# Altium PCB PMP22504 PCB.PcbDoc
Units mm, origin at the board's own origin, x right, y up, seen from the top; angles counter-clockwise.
Board outline 85 x 42.5 mm, 2 copper layers (Top Layer, Bottom Layer), stack 1.575 mm thick; 21 components, 12 nets, 56 pads, 21 vias.
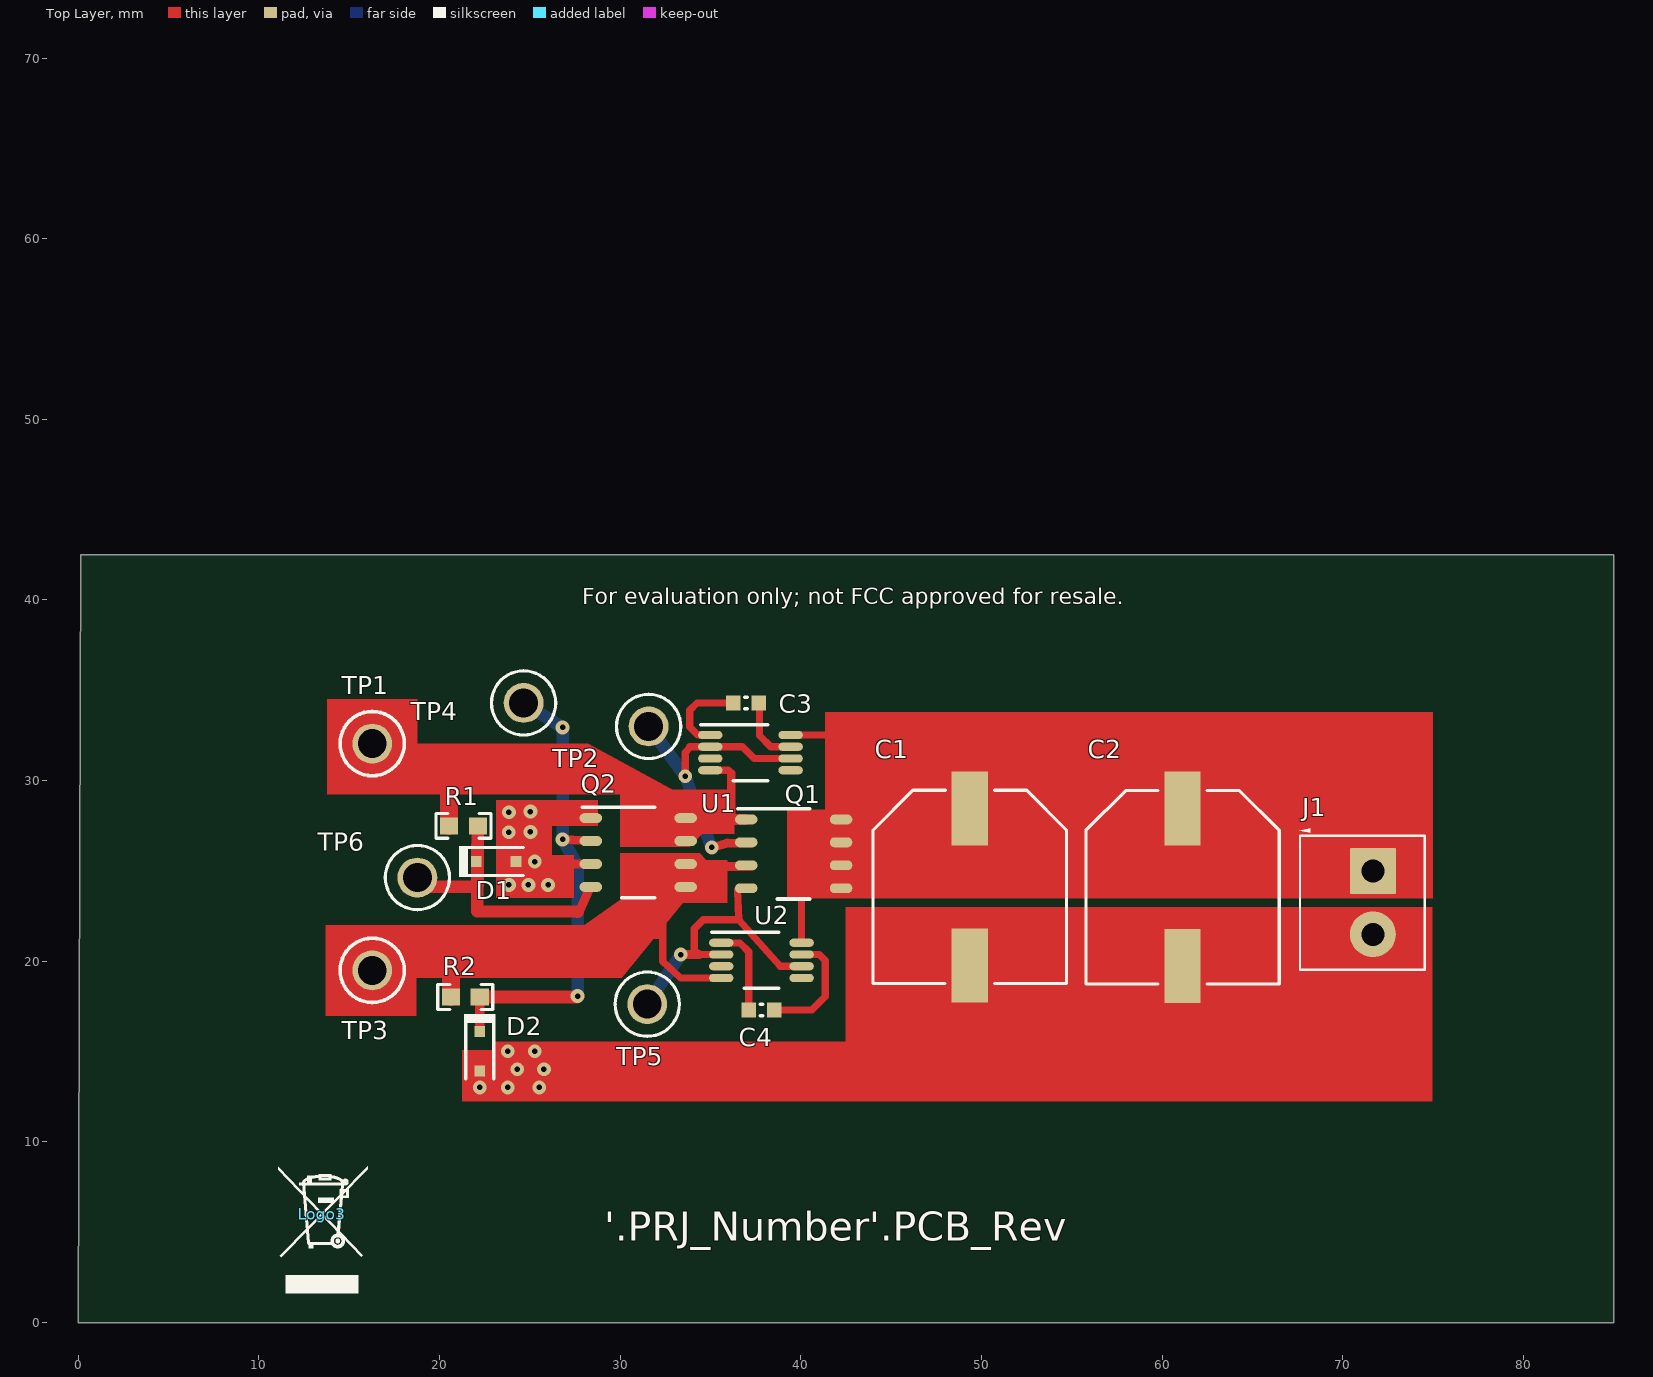
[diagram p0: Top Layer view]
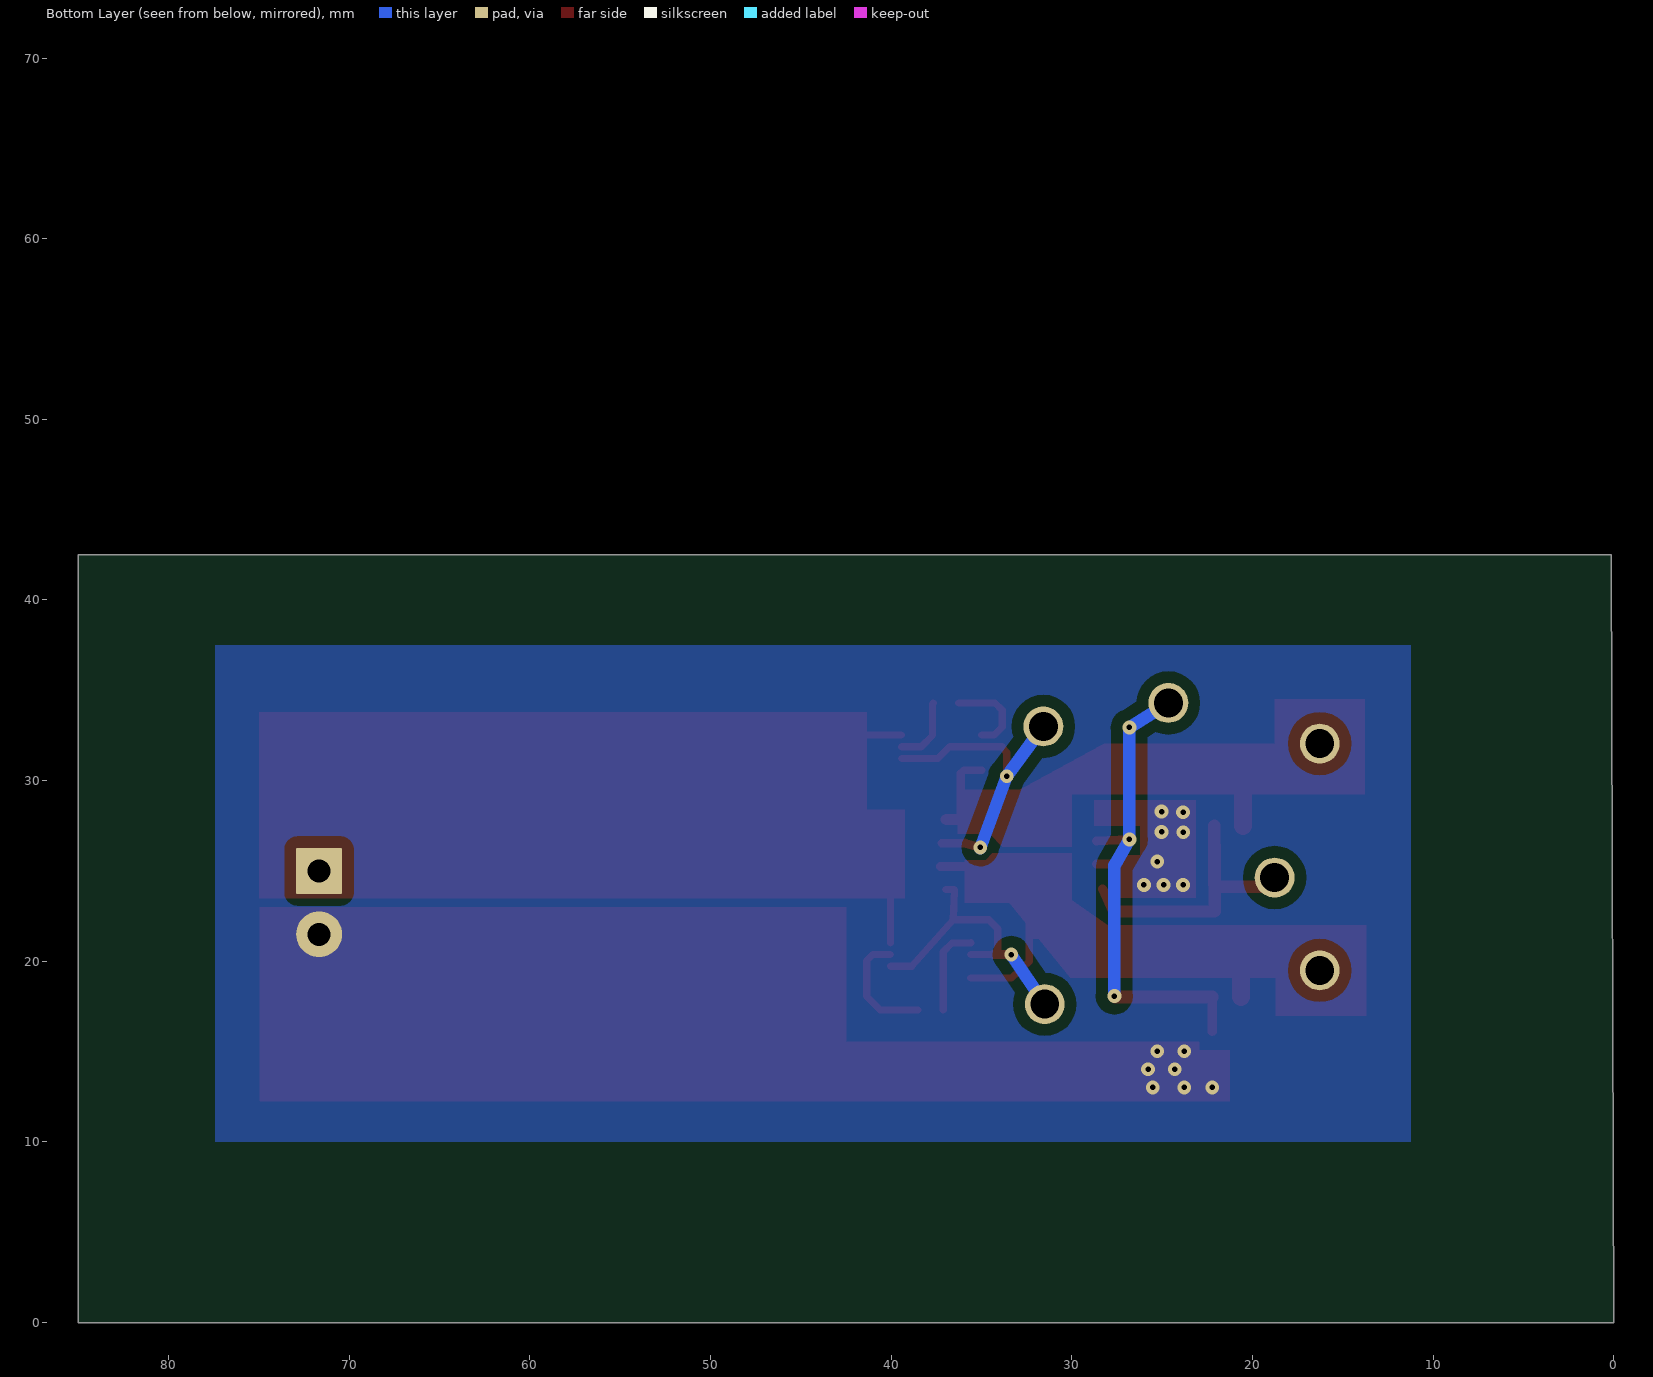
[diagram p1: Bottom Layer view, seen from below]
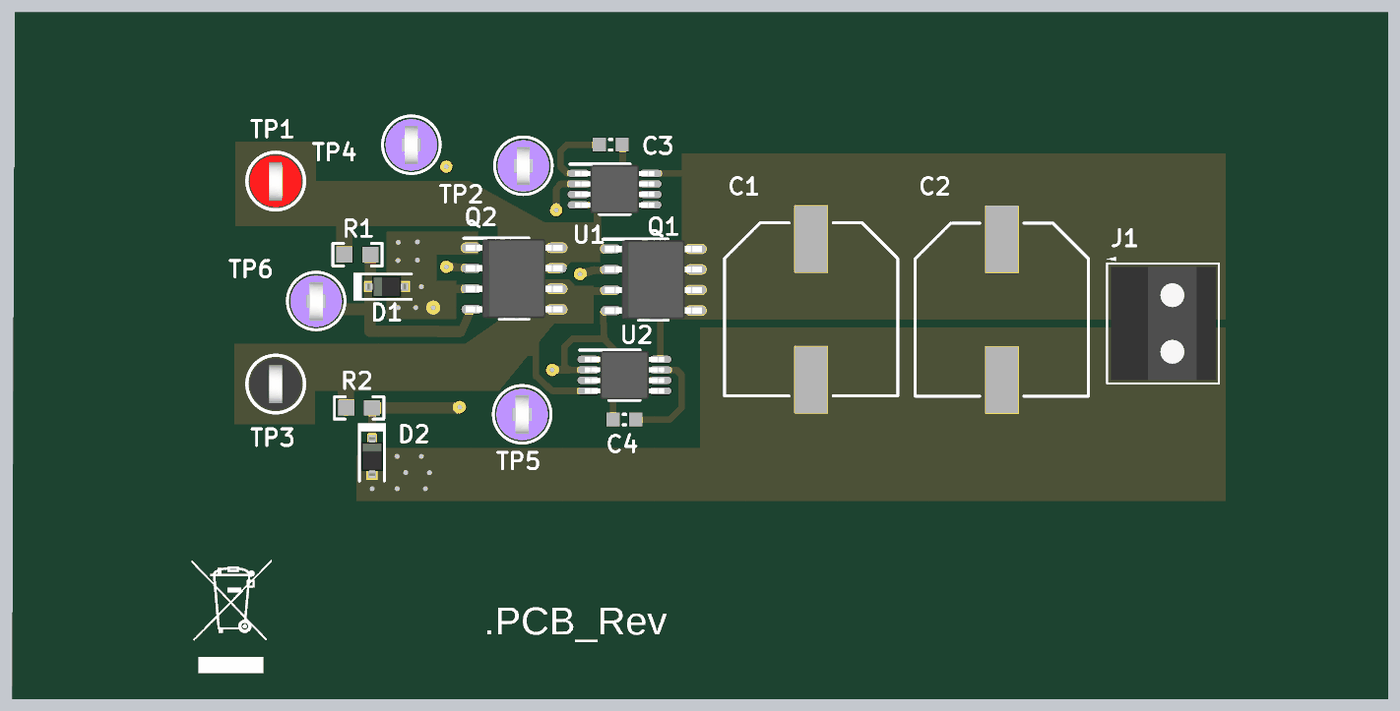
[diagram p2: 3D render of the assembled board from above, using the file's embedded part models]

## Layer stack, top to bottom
Top Solder: solder mask 0.0102, Solder Resist, Dk 3.5
Top Layer: signal copper 0.0356
Dielectric1: core 1.5037, FR-4, Dk 4.8
Bottom Layer: signal copper 0.0356
Bottom Solder: solder mask 0.0102, Solder Resist, Dk 3.5

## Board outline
0,0 85,0 85,42.5 0.142,42.5

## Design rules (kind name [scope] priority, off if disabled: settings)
AcuteAngle [All] p1: minimum=4.50000000000000E+0001 checktracksonly=FALSE
AssemblyTestPointUsage [All] p1: valid=2
BoardOutlineClearance BoardOutlineClearance_MountingHoles [OnCopper and InComponentClass('Mounting Holes')] p1: gap=1 ignorepadtopadclearanceinfootprint=FALSE
BoardOutlineClearance BoardOutlineClearance_Poly [OnCopper and IsPoly] p2: gap=0.635 ignorepadtopadclearanceinfootprint=FALSE
BoardOutlineClearance [OnCopper and Not InComponentClass('Logo') and not InComponentClass('FiducialMark') and not InRegion(1000,500,4000,800) and not InPoly] p3: gap=1.905 ignorepadtopadclearanceinfootprint=FALSE
Clearance Clearance_Keepouts [((IsTrack Or IsArc) And Not InPoly) And IsFree and IsKeepOut vs ((IsTrack Or IsArc) And Not InPoly) And IsFree and IsKeepOut] p1: gap=0 ignorepadtopadclearanceinfootprint=FALSE
Clearance Clearance_Poly [InPolygon] p2: gap=0.635 ignorepadtopadclearanceinfootprint=TRUE
Clearance Clearance_FiducialMark [IsKeepOut and InComponentClass('FiducialMark') vs IsPad and InComponentClass('FiducialMark')] p3: gap=0 ignorepadtopadclearanceinfootprint=FALSE
Clearance [All] p4: gap=0.2 ignorepadtopadclearanceinfootprint=TRUE
ComponentClearance ComponentClearance_MountingHoles_FiducialMarks [InComponentClass('Mounting Holes') vs InComponentClass('FiducialMark')] p1: gap=1.27 collisioncheckmode=3 verticalgap=0.254 showdistances=FALSE
ComponentClearance ComponentClearance_Shunt [InComponentClass('Header') vs InComponentClass('Shunt')] p2: gap=0 collisioncheckmode=3 verticalgap=0 showdistances=FALSE
ComponentClearance ComponentClearance_Logo [InComponentClass('Logo')] p3: gap=1.27 collisioncheckmode=3 verticalgap=0.254 showdistances=FALSE
ComponentClearance ComponentClearance_ScrewToNut [(HasFootprint('NY PMS 440 0025 PH')) vs (HasFootprint('Keystone_1902C'))] p4: gap=0.127 collisioncheckmode=3 verticalgap=0.254 showdistances=FALSE
ComponentClearance ComponentClearance_MountingHoles [InComponentClass('Mounting Holes')] p5: gap=6.35 collisioncheckmode=3 verticalgap=2540 showdistances=FALSE
ComponentClearance ComponentClearance_SmallPassives [HasFootprint('0201*') or HasFootprint('0402*') or HasFootprint('0508') or HasFootprint('0603*') or HasFootprint('0612') or HasFootprint('0805*') or HasFootprint('0815*') or HasFootprint('0830*') or HasFootprint('1206*') or HasFootprint('1210*') or HasFootprint('1808*') or HasFootprint('1812*') or HasFootprint('1825*') or HasFootprint('2010*') or HasFootprint('2220*') or HasFootprint('2225*') or HasFootprint('2512*') or HasFootprint('2728*') or HasFootprint('3518*') vs HasFootprint('0201*') or HasFootprint('0402*') or HasFootprint('0508') or HasFootprint('0603*') or HasFootprint('0612') or HasFootprint('0805*') or HasFootprint('0815*') or HasFootprint('0830*') or HasFootprint('1206*') or HasFootprint('1210*') or HasFootprint('1808*') or HasFootprint('1812*') or HasFootprint('1825*') or HasFootprint('2010*') or HasFootprint('2220*') or HasFootprint('2225*') or HasFootprint('2512*') or HasFootprint('2728*') or HasFootprint('3518*')] p6: gap=0.38 collisioncheckmode=3 verticalgap=0.254 showdistances=FALSE
ComponentClearance ComponentClearance_THtoSMT [IsThruComponent vs IsSMTComponent] p7: gap=1.016 collisioncheckmode=3 verticalgap=0.762 showdistances=FALSE
ComponentClearance ComponentClearance_THtoTH [IsThruComponent vs IsThruComponent] p8: gap=0.762 collisioncheckmode=3 verticalgap=0.762 showdistances=FALSE
ComponentClearance [All] p9: gap=0.762 collisioncheckmode=3 verticalgap=0.254 showdistances=FALSE
DiffPairsRouting [All] p1: maxlimit=2.54 minlimit=0.254 mostfreqgap=0.254 toplayer_minwidth=0.381 toplayer_maxwidth=0.381 toplayer_prefwidth=0.381 bottomlayer_minwidth=0.381 bottomlayer_maxwidth=0.381 bottomlayer_prefwidth=0.381 maxuncoupledlength=25.4
FabricationTestPointUsage TestPointUsage [All] p1: valid=2 allowmultiple=FALSE
FabricationTestpoint Testpoint [All] p1: side=3 testpointundercomponent=TRUE minsize=1.016 maxsize=2.54 preferedsize=1.524 minholesize=0 maxholesize=1.016 preferedholesize=0.813 testpointgrid=0.025 allowsidetop=TRUE allowsidebottom=TRUE usegrid=TRUE gridtolerance=0
FanoutControl Fanout_LCC [IsLCC] p1: bgadir=Out bgaviamode=Centered fanoutstyle=Auto fanoutdirection=Alternating viagrid=0.025 // Fanout_LCC (Default Rule)
FanoutControl Fanout_BGA [IsBGA] p2: bgadir=Out bgaviamode=Centered fanoutstyle=Auto fanoutdirection=Alternating viagrid=0.025 // Fanout_BGA (Default Rule)
FanoutControl Fanout_Default [All] p4: bgadir=Out bgaviamode=Centered fanoutstyle=Auto fanoutdirection=Alternating viagrid=0.025 // Fanout_Default (Default Rule)
FanoutControl Fanout_Small [(CompPinCount < 5)] p5: bgadir=Out bgaviamode=Centered fanoutstyle=Auto fanoutdirection=OutThenIn viagrid=0.025 // Fanout_Small (Default Rule)
HoleSize [All] p1: absolutevalues=TRUE maxlimit=6.375 minlimit=0.2 maxpercent=80.000 minpercent=20.000
MinimumAnnularRing MinimumAnnularRing_ThermalPadVias [IsVia and InAnyComponent] p1: minimumring=0.15
MinimumAnnularRing [All] p2: minimumring=0.2
MinimumSolderMaskSliver MinimumSolderMaskSliver_Logo [InComponentClass('Logo') vs InComponentClass('Logo')] p1: minsoldermaskwidth=0.018
MinimumSolderMaskSliver [All] p2: minsoldermaskwidth=0.1
PlaneConnect [All] p1: planeconnectstyle=Relief reliefexpansion=0.254 reliefentries=4 reliefconductorwidth=0.254 reliefairgap=0.254
PolygonConnect [All] p1: connectstyle=Direct reliefconductorwidth=0.254 reliefentries=4 polygonreliefangle="90 Angle" airgapwidth=0.254
RoutingVias ThermalPadVias [IsVia and InAnyComponent] p1: holewidth=0.2 width=0.5 viastyle="Through Hole" minholewidth=0.2 minwidth=0.5 maxholewidth=0.33 maxwidth=0.6
RoutingVias [All] p2: holewidth=0.406 width=0.864 viastyle="Through Hole" minholewidth=0.2 minwidth=0.66 maxholewidth=1.016 maxwidth=1.651
SilkToBoardRegionClearance [Not ((IsComment or IsDesignator) And (Hide <> 'False')) and not InRegion(1000,500,4000,800)] p1:
SilkToSilkClearance SilkToSilkClearance_Pb-FreeLogo [(HasFootprint('Pb-Free_Overlay_Medium') OR HasFootprint('Pb-Free_Overlay_Small')) vs (HasFootprint('Pb-Free_Overlay_Medium') OR HasFootprint('Pb-Free_Overlay_Small'))] p1: silktosilkclearance=0
SilkToSilkClearance [All] p2: silktosilkclearance=0.1
SilkToSolderMaskClearance SilkToComponentPadClearance [(IsPad or IsFill or IsRegion) and InAnycomponent] p1: minsilkscreentomaskgap=0.127 clearancetoexposedcopper=TRUE
SilkToSolderMaskClearance "Silk to Solder Mask Opening" [All] p2: minsilkscreentomaskgap=0.1 clearancetoexposedcopper=FALSE
SolderMaskExpansion [All] p1: expansion=0.05
UnRoutedNet [All] p1: checkbadconnections=TRUE
Width [All] p1: maxlimit=2.54 minlimit=0.152 preferedwidth=0.254 checkconnectedcopper=TRUE
14 further rules are at their usual default settings.

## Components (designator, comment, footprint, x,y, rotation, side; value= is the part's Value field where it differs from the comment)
C1 "CBULK" SM_RADIAL_G 49.351,24.117 r270 top value=220uF
C2 "CBULK" SM_RADIAL_G 61.132,24.101 r270 top value=330uF
C3 "GRM188Z71C225KE43" 0603L 36.97,34.301 r180 top value=2.2uF
C4 "GRM188Z71C225KE43" 0603L 37.817,17.301 r180 top value=2.2uF
D1 "MMSZ5242BS-7-F" SOD-323 23.129,25.524 r0 top value=12V
D2 "MMSZ5242BS-7-F" SOD-323 22.228,15.022 r270 top value=12V
J1 "ED555/2DS" TERM_BLK_ED555-2DS 71.667,25 r270 top
Logo2 "FCC disclaimer" FCC_disclaimer 0.5,-26.75 r0 top
Logo3 "WEEE logo" WEEE_Minimum 13.5,6 r0 top
Q1 "CSD88539ND" D0008A_L 39.603,25.951 r0 top value=60V
Q2 "CSD88539ND" D0008A_L 31,26.022 r0 top value=60V
R1 "RC0603FR-0712KL" 0603 21.326,27.499 r180 top value=12.0k
R2 "RC0603FR-0712KL" 0603 21.428,18.022 r180 top value=12.0k
TP1 "LINE" Keystone5010 16.276,32.051 r0 top
TP2 "5129" Keystone5129 31.576,33 r0 top
TP3 "NEUTRAL" Keystone5011 16.276,19.5 r0 top
TP4 "5129" Keystone5129 24.654,34.301 r0 top
TP5 "5129" Keystone5129 31.499,17.626 r0 top
TP6 "5129" Keystone5129 18.776,24.636 r0 top
U1 "LM74610QDGKRQ1" DGK0008A_N 37.209,31.551 r0 top
U2 "LM74610QDGKRQ1" DGK0008A_N 37.817,20.051 r0 top

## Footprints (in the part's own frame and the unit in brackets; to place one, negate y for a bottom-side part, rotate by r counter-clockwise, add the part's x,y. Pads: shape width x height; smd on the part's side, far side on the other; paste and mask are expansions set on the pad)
0603 [mm] "0603 from SM-752 data"
  rect 1x0.95 smd: 1(-0.8,0) 2(0.8,0)
  silkscreen extent -1.52,-0.69 1.52,0.69, body extent -0.87,-0.47 0.87,0.47, height 1
0603L [mm] "0603 from SM-752 data"
  rect 0.8x0.85 smd: 1(-0.7,0) 2(0.7,0)
  silkscreen extent -0.07,-0.33 0.07,0.33, body extent -0.87,-0.47 0.87,0.47, height 1
D0008A_L [mm] "SOIC, 8-Leads, Body 4.9x3.9mm, Pitch 1.27mm, IPC High Density"
  oval 1.25x0.55 smd: 1(-2.625,1.905) 2(-2.625,0.635) 3(-2.625,-0.635) 4(-2.625,-1.905) 5(2.625,-1.905) 6(2.625,-0.635) 7(2.625,0.635) 8(2.625,1.905)
  silkscreen extent -3.1,-2.5 0.9,2.5, body extent -3,-2.45 3,2.45, height 1.63
DGK0008A_N [mm] "TSOP, 8-Leads, Body 3x3mm, Pitch 0.65mm, IPC Medium Density"
  oval 1.35x0.45 smd: 1(-2.225,0.975) 2(-2.225,0.325) 3(-2.225,-0.325) 4(-2.225,-0.975) 5(2.225,-0.975) 6(2.225,-0.325) 7(2.225,0.325) 8(2.225,0.975)
  silkscreen extent -2.75,-1.55 0.95,1.55, body extent -2.45,-1.5 2.45,1.5, height 0.96
FCC_disclaimer [mm]
Keystone5010 [mil] "Keystone Multipurpose loops"
  round 87 hole 63: 1(0,0)
  silkscreen extent -70,-70 70,70, body extent -63,-63 63,62, height 319
Keystone5011 [mil] "Keystone Multipurpose loops"
  round 87 hole 63: 1(0,0)
  silkscreen extent -70,-70 70,70, body extent -63,-63 63,62, height 319
Keystone5129 [mil] "Keystone Multipurpose loops"
  round 87 hole 63: 1(0,0)
  silkscreen extent -70,-70 70,70, body extent -63,-63 63,62, height 319
SM_RADIAL_G [mm] "10 x 10.2mm:  Panasonic G"
  rect 4.1x2 smd: 1(-4.35,0) 2(4.35,0)
  silkscreen extent -5.35,-5.35 5.35,5.35, body extent -5.25,-5.25 5.25,5.25, height 10.5
SOD-323 [mm] "NXP recommended land pattern"
  rect 0.6x0.6 smd paste-0.05: 1(-1.1,0) 2(1.1,0)
  silkscreen extent -2.06,-0.86 1.53,0.86, body extent -1.3,-0.67 1.3,0.68, height 1.1
TERM_BLK_ED555-2DS [mil]
  rrect4% 100x100 hole 50: 1(0,0)
  round 100 hole 50: 2(138,0)
  silkscreen extent -93,-161 215,113, body extent -69,-150 207,106, height 323
WEEE_Minimum [mm] "WEEElie bin"
  silkscreen extent -2.42,-4.38 2.52,2.65

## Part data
C1: library part CMP-0011180-2, "CAP, AL, 220 uF, 50 V, +/- 20%, 0.18 ohm, AEC-Q200 Grade 2, SMD", Cap_Case=G, Manufacturer=Panasonic, PartNumber=EEE-FK1H221GP, Supplier Part Number 1=PCE4324CT-ND, Tolerance_%=20%, Value1="0.18 ohm", Value2=50V, ValueDisplayed=220uF
C2: library part CMP-0860442-1, "CAP, AL, 330 µF, 50 V, +/- 20%, 0.12 ohm, AEC-Q200 Grade 2, SMD", Cap_Case=10x10.2mm, Manufacturer=Panasonic, PartNumber=EEE-FT1H331AP, Tolerance_%=20%, Value1="0.12 ohm", Value2=50V, ValueDisplayed=330µF
C3 C4: library part CMP-0007499-1, "CAP, CERM, 2.2 uF, 16 V, +/- 10%, X7R, 0603", Cap_Case=0603, Manufacturer=MuRata, Supplier Part Number 1=81-GRM188Z71C225KE3D, TempCo=X7R, Tolerance_%=10%, Value1=Unknown, Value2=16V, ValueDisplayed=2.2uF
D1 D2: library part CMP-0005831-4, "Diode, Zener, 12 V, 200 mW, SOD-323", Manufacturer="Diodes Inc.", Power_W=200mW, Value1=0.2W
J1: library part CMP-0074913-1, "Terminal Block, 3.5mm Pitch, 2x1, TH", Color=Grey, Current_A=6A, Manufacturer="On-Shore Technology", Supplier Part Number 1=ED1514-ND, Voltage_V=150V
Logo2: library part CMP-0074847-1, "FCC_disclaimer"
Logo3: library part CMP-0074769-1
Q1 Q2: library part CMP-0000829-2, "MOSFET, 2-CH, N-CH, 60 V, 6.3 A, D0008A (SOIC-8)", Alternate Manufacturer=None, Manufacturer="Texas Instruments", Supplier Part Number 1=296-37304-1-ND, Value2="7.2 nC"
R1 R2: library part CMP-0022779-5, "RES, 12.0 k, 1%, 0.1 W, 0603", Manufacturer=Yageo, Power_W=100mW, Supplier Part Number 1=311-12.0KHRCT-ND, TempCo="100 ppm/C", Tolerance_%=1%, Value2=0.1W, Value_Code=12k0, ValueDisplayed=12.0k
TP1: library part CMP-0055147-1, "Test Point, Multipurpose, Red, TH", Color=Red, Manufacturer=Keystone, PartNumber=5010, Supplier Part Number 1=36-5010-ND
TP2 TP4 TP5 TP6: library part CMP-0055160-1, "Test Point, Multipurpose, Purple, TH", Color=Purple, Manufacturer=Keystone, Supplier Part Number 1=36-5129-ND
TP3: library part CMP-0055148-1, "Test Point, Multipurpose, Black, TH", Color=Black, Manufacturer=Keystone, PartNumber=5011, Supplier Part Number 1=36-5011-ND
U1 U2: library part CMP-0076397-2, "Zero Iq Reverse Polarity Protection Smart Diode Controller, DGK0008A (VSSOP-8)", Alternate Manufacturer="Texas Instruments"

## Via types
v1: diameter 0.762, hole 0.305, Top Layer to Bottom Layer, tented top, 14 vias
v2: diameter 0.762, hole 0.305, Top Layer to Bottom Layer, 7 vias

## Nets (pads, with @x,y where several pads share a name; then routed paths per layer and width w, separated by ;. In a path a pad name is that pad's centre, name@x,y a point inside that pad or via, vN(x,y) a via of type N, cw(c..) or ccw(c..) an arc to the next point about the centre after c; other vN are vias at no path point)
GND: C1.2 C2.2 D1.2 D2.2 J1.2 Q2.1 Q2.3 | length 1.6
  Top Layer w0.5: 27,25.387 Q2.3@28.625,25.387
  other v1: 22.228,13.022 23.776,13.022 25.526,13.022 24.306,14.022 25.776,14.022 23.776,15.022 25.276,15.022 23.843,24.228 24.924,24.228 25.277,25.524 23.826,27.143 25.029,27.162 23.843,28.257 25.029,28.291
  other v2: 26.009,24.228
NetC1_1: C1.1 C2.1 J1.1 Q1.5 Q1.6 Q1.7 Q1.8 U1.8 U2.8 | length 6.2
  Top Layer w0.4: U1.8 42.701,32.526 ; 40.03,23.97 U2.8
NetC3_1: C3.1 U1.7 | length 3.8
  Top Layer w0.4: C3.1 37.709,34.263 37.709,32.498 38.331,31.876 U1.7
NetC3_2: C3.2 U1.1 | length 4.8
  Top Layer w0.4: U1.1 34.3,32.526 33.851,32.976 33.851,33.899 34.253,34.301 C3.2
NetC4_1: C4.1 U2.7 | length 6.6
  Top Layer w0.4: C4.1 40.601,17.301 41.351,18.051 41.351,20.051 41.026,20.376 U2.7
NetC4_2: C4.2 U2.1 | length 5
  Top Layer w0.4: U2.1 35.605,21.014 36.639,21.014 37.117,20.535 C4.2
NetD1_1: D1.1 Q2.4 R1.1 TP6.1 | length 15.2
  Top Layer w0.5: 27.75,22.75 Q2.4@28.294,23.992
  Top Layer w0.7: TP6.1 19.287,24.124 22.094,24.124 ; R1.1 22.106,25.522 22.094,22.772 27.645,22.75
NetD2_1: D2.1 Q2.2 R2.1 TP4.1 | length 26.8
  Top Layer w0.5: D2.1 R2.1 ; v2(26.814,26.75) Q2.2@28.625,26.657 ; v2@27.593,18.022 v2(27.645,18.074)
  Top Layer w0.7: R2.1 v2@27.593,18.022
  Bottom Layer w0.7: TP4.1 v2(26.814,32.945) v2(26.814,26.75) 27.645,25.305 v2(27.645,18.074)
NetQ1_1: Q1.1 Q2.7 Q2.8 R1.2 TP1.1 U1.4 | length 7.9
  Top Layer w0.4: U1.4 35.992,30.576 36.148,30.421
  Top Layer w0.45: 36.148,27.787 36.148,30.421
  Top Layer w0.6: 35.83,27.856 Q1.1@36.964,27.851
  Top Layer w1: R1.2 20.526,30.443
NetQ1_2: Q1.2 TP2.1 U1.2 U1.6 | length 17.4
  Top Layer w0.4: v2(33.604,30.25) 33.606,31.551 33.851,31.876 U1.2 36.776,31.876 37.426,31.226 U1.6
  Top Layer w0.45: 35.926,26.537 Q1.2@37.204,26.537
  Top Layer w0.5: v2(35.067,26.301) 35.926,26.537
  Bottom Layer w0.7: TP2.1 v2(33.604,30.25) v2@35.067,26.252
NetQ1_3: Q1.3 Q2.5 Q2.6 R2.2 TP3.1 U2.4 | length 13
  Top Layer w0.4: 31.627,21.423 32.351,21.423 ; 32.351,24.47 32.351,22 32.351,20 33.351,19.076 U2.4
  Top Layer w0.5: 35.425,25.247 Q1.3@37.267,25.249
  Top Layer w1: 20.603,20.335 R2.2
NetQ1_4: Q1.4 TP5.1 U2.2 U2.6 | length 16.6
  Top Layer w0.4: U2.2 34.351,20.376 34.101,20.626 34.101,21.801 34.601,22.301 36.564,22.301 ; Q1.4@37,23.97 36.495,23.97 36.564,22.301 ; U2.6 38.851,19.726 36.564,22.301
  Top Layer w0.5: v2(33.351,20.376) 34.351,20.376
  Bottom Layer w0.7: TP5.1 v2(33.351,20.376)
pads on no net: U1.3 U1.5 U2.3 U2.5

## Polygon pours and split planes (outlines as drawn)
GND on Bottom Layer "BOTTOM_LAYER_GND_P002" (solid, remove dead copper, pour order 2): 11.25,10 77.415,10 77.415,37.5 11.25,37.5

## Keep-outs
Keep-Out Layer:
  text ".Layer_Name" at 14.656,-21.806 h1.52

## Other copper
Top Layer:
  region: 41.434,70.101
  region net GND: 23.5,15.075 21.25,15.075 21.25,12.25 23.5,12.25
  region net NetQ1_3: 13.713,17 18.713,17 18.713,22 13.713,22
  region: 22.832,17.799
  region: 21.326,21.874
  region net NetQ1_3: 33.75,23.572 30.074,19.076 13.713,19.076 13.713,22 28,22 30.25,23.572
  region: 28.776,26.022
  region net GND: 23.129,23.522 27.426,23.522 27.426,25.882 26.202,25.882 26.202,27.499 28.764,27.499 28.764,28.915 23.129,28.915
  region: 14.276,27.954
  region net NetQ1_1: 13.776,34.5 18.776,34.5 18.776,29.25 13.776,29.25
  region net NetQ1_1: 33.343,29.25 28.246,32.051 13.776,32.051 13.776,29.25
  region net NetQ1_1: 30,26.351 33.851,26.351 34.554,27.054 34.554,27.5 30,27.5
  region net NetQ1_3: 30,25.976 34.411,25.976 34.759,25.583 34.897,25.583 35.926,25.583 35.926,23.25 30,23.25
  region net GND: 43.351,15.551 22.951,15.551 22.951,12.25 43.351,12.25
  region net GND: 42.5,23 74.95,23 74.95,12.25 42.5,12.25
  region net NetQ1_1: 30,29.5 36.32,29.5 36.32,27.082 36.351,27.051 30,27.051
  region net NetC1_1: 39.25,23.5 39.25,28.401 41.351,28.401 41.351,33.776 74.967,33.776 74.969,23.5
  text ".Layer_Name" at 14.656,-21.806 h1.52
Bottom Layer:
  text ".Layer_Name" at 14.656,-21.806 h1.52

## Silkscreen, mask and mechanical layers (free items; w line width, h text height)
Top Overlay:
  text "'.PRJ_Number'.PCB_Rev" at 29.13,4.009 h2.75
  text ".Layer_Name" at 14.656,-21.806 h1.52
Bottom Overlay:
  text ".Layer_Name" at 14.656,-21.806 h1.52
Top Paste:
  text ".Layer_Name" at 14.656,-21.806 h1.52
Bottom Paste:
  text ".Layer_Name" at 14.656,-21.806 h1.52
Top Solder:
  text ".Layer_Name" at 14.656,-21.806 h1.52
  text ".Layer_Name" at 14.656,-21.806 h1.52
Bottom Solder:
  text ".Layer_Name" at 14.656,-21.806 h1.52
Drill Guide:
  text ".Layer_Name" at 14.656,-21.806 h1.52
M1 Board Outline:
  the board outline again, w0.254
  text ".Layer_Name" at 14.656,-21.806 h1.52
M2 Board Dimensions:
  rectangle: 0,-6.985 3.175,-3.81
  rectangle: 3.175,-10.16 12.7,-6.985
  lines w0.178: 0,-6.985 25.4,-6.985 ; 3.175,-10.16 3.175,-3.81 ; 6.35,-10.16 6.35,-3.81 ; 12.7,-10.16 12.7,-3.81 ; 19.05,-10.16 19.05,-3.81 ; 0,-10.16 25.4,-10.16 25.4,-3.81 0,-3.81 0,-10.16
  text ".Layer_Name" at 14.656,-21.806 h1.52
M3 3D STEP Top:
  text ".Layer_Name" at 14.656,-21.806 h1.52
M4 3D STEP Bottom:
  text ".Layer_Name" at 14.656,-21.806 h1.52
M5 Assembly Top:
  lines w0.254: -7.417,-23.626 160.223,-23.626 ; -7.417,-18.462 160.274,-18.462 ; -7.417,-13.297 -7.417,-28.791 94.31,-28.791 160.274,-28.791 160.274,-13.297 -7.404,-13.297 -7.404,-28.791 32.614,-28.791 ; 55.194,-28.791 55.194,-13.297 ; 87.376,-18.462 87.376,-13.297 ; 108.712,-18.462 108.712,-13.297 ; 124.511,-28.956 124.511,-23.804
  text "COMPONENTS MARKED 'DNP' SHOULD NOT BE POPULATED." at 29.299,-8.09 h1.52
  text "ASSEMBLY VARIANT:" at 29.286,-11.024 h1.52
  text ".VariantName" at 55.601,-11.024 h1.52
  text "PCB VIEWED FROM TOP SIDE" at -5.804,-16.654 h1.52
  text "BOARD #:" at 57.099,-16.654 h1.52
  text ".PRJ_Number" at 70.955,-16.654 h1.52
  text "REV:" at 92.405,-16.654 h1.52
  text ".PCB_Rev" at 99.809,-16.654 h1.52
  text "SVN REV:" at 113.69,-16.654 h1.52
  text ".VersionControl_RevNumber" at 126.543,-16.654 h1.52
  text "TID #:" at 57.099,-21.819 h1.52
  text ".TID" at 70.955,-21.819 h1.52
  text "PLOT NAME =" at -5.804,-27.034 h1.52
  text ".plot_File_Name" at 14.656,-27.034 h1.52
  text "GENERATED    :" at 57.15,-27.034 h1.52
  text ".Print_Date" at 79.235,-27.034 h1.52
  text ".Print_Time" at 97.752,-27.034 h1.52
  text "TEXAS INSTRUMENTS" at 129.87,-27.034 h1.52
M6 Assembly Bottom:
  lines w0.254: -7.429,-18.474 160.261,-18.474 ; -7.379,-23.639 160.261,-23.639 ; 28.334,-28.969 28.334,-23.817 ; 44.133,-18.474 44.133,-13.31 ; 65.468,-18.474 65.468,-13.31 ; 97.65,-28.804 97.65,-13.31 ; 120.231,-28.804 160.249,-28.804 160.249,-13.31 -7.429,-13.31 -7.429,-28.804 58.534,-28.804 160.261,-28.804 160.261,-13.31
  text "COMPONENTS MARKED 'DNP' SHOULD NOT BE POPULATED." at 154.991,-8.077 h1.52
  text ".VariantName" at 128.473,-11.024 h1.52
  text "ASSEMBLY VARIANT:" at 154.864,-11.024 h1.52
  text ".VersionControl_RevNumber" at 26.302,-16.667 h1.52
  text "SVN REV:" at 39.154,-16.667 h1.52
  text ".PCB_Rev" at 53.035,-16.667 h1.52
  text "REV:" at 60.439,-16.667 h1.52
  text ".PRJ_Number" at 81.89,-16.667 h1.52
  text "BOARD #:" at 95.745,-16.667 h1.52
  text "PCB VIEWED FROM BOTTOM SIDE" at 158.648,-16.667 h1.52
  text ".TID" at 81.89,-21.831 h1.52
  text "TID #:" at 95.745,-21.831 h1.52
  text "TEXAS INSTRUMENTS" at 22.974,-27.047 h1.52
  text ".Print_Time" at 55.093,-27.047 h1.52
  text ".Print_Date" at 73.609,-27.047 h1.52
  text "GENERATED    :" at 95.694,-27.047 h1.52
  text ".plot_File_Name" at 138.189,-27.047 h1.52
  text "PLOT NAME =" at 158.648,-27.047 h1.52
M9 Title Sheet:
  drawing of 57 lines, arcs and shapes, not listed
  text "1" at 18.792,204.127 h1.78
  text "2" at 82.182,204.127 h1.78
  text "3" at 145.411,204.127 h1.78
  text "4" at 209.08,204.127 h1.78
  text "5" at 272.555,204.127 h1.78
  text "6" at 336.182,204.127 h1.78
  text "A" at -10.579,175.095 h1.78
  text "A" at 365.341,175.095 h1.78
  text "B" at -10.579,114.643 h1.78
  text "B" at 365.341,114.643 h1.78
  text "C" at -10.579,54.318 h1.78
  text "C" at 365.341,54.318 h1.78
  text "PROJECT TITLE:" at 288.125,7.048 h1.14
  text ".PRJ_Title" at 289.395,3.662 h1.78
  text "DESIGNED FOR:" at 288.125,-0.597 h1.14
  text ".PRJ_Customer" at 289.395,-4.153 h1.78
  text "D" at -10.579,-5.88 h1.78
  text "D" at 365.341,-5.88 h1.78
  text "FILE NAME:" at 288.125,-8.217 h1.14
  text ".PCB_File_Name_No_Path" at 289.395,-11.265 h1.78
  text "Texas Instruments (TI) and/or its licensors do not warrant the accuracy or completeness of this specification" at 161.9,-15.376 h1.14
  text "ENGINEER:" at 288.125,-15.583 h1.14
  text "LAYOUT BY:" at 326.352,-15.583 h1.14
  text "or any information contained therein. TI and/or its licensors do not warrant that this design will meet" at 160.757,-18.237 h1.14
  text ".PRJ_Engineer" at 289.395,-19.52 h1.78
  text ".PCB_Layout" at 327.635,-19.52 h1.78
  text "the specifications, will be suitable for your application or fit for any particular purpose, or will operate in" at 160.757,-21.099 h1.14
  text ".Layer_Name" at 14.656,-21.806 h1.52
  text "ALTIUM DESIGNER VERSION:" at 326.352,-23.457 h1.14
  text "an implementation. TI and/or its licensors do not warrant that the design is production worthy. You should" at 160.757,-23.961 h1.14
  text "completely validate and test your design implementation to confirm the system functionality for your application." at 161.9,-26.822 h1.14
  text ".print_Scale" at 289.395,-26.843 h1.78
  text ".Application_BuildNumber" at 327.635,-26.843 h1.78
  text "1" at 18.792,-32.093 h1.78
  text "2" at 82.182,-32.093 h1.78
  text "3" at 145.411,-32.093 h1.78
  text "4" at 209.08,-32.093 h1.78
  text "5" at 272.555,-32.093 h1.78
  text "6" at 336.182,-32.093 h1.78
M10 Fab Notes:
  drawing of 189 lines, arcs and shapes, not listed
  text "DESIGN INFORMATION" at 314.503,161.447 h1.52
  text "MIN. TRACK WIDTH:" at 298.131,158.091 h1.52
  text "8" at 325.976,158.091 h1.52
  text "MIL" at 329.907,158.091 h1.52
  text "MIN. CLEARANCE:" at 298.131,154.938 h1.52
  text "0.2" at 324.452,154.938 h1.52
  text "mm" at 329.907,154.938 h1.52
  text "MIN. VIA PAD SIZE:" at 298.131,151.785 h1.52
  text "24" at 325.214,151.785 h1.52
  text "MIL" at 329.907,151.785 h1.52
  text "0.05mm (2MIL)" at 315.784,148.486 h1.52
  text "MINIMUM ANNULAR RING" at 289.769,148.277 h1.52
  text "EXTERNAL" at 333.768,148.277 h1.52
  text "PER" at 294.849,145.48 h1.52
  text "IPC-D-275 CLASS 2 LEVEL C" at 300.437,145.48 h1.52
  text "MIL, HOLES" at 338.238,142.928 h1.52
  text "+/-" at 328.27,142.709 h1.52
  text "+/-" at 349.961,142.709 h1.52
  text "REGISTRATION TOLERANCES:" at 289.769,142.682 h1.52
  text "METAL" at 320.243,142.682 h1.52
  text "5" at 334.879,142.683 h1.52
  text "3" at 356.037,142.683 h1.52
  text "MIL" at 358.99,142.682 h1.52
  text "HOLE SIZE TOLERANCE (UNLESS OTHERWISE SPECIFIED):" at 289.769,140.185 h1.52
  text "+/-" at 349.961,140.112 h1.52
  text "3" at 356.037,140.085 h1.52
  text "MIL" at 358.99,140.085 h1.52
  text "MATERIAL:" at 287.87,136.589 h1.52
  text "FR-4 High Tg" at 312.926,133.324 h1.52
  text "X" at 309.257,133.122 h1.52
  text "FR-408" at 298.563,133.007 h1.52
  text "OTHER" at 336.358,133.007 h1.52
  text "62 MIL (1.6mm) +/-10%" at 306.694,129.374 h1.52
  text "X" at 303.643,129.312 h1.52
  text "THICKNESS:" at 289.769,129.165 h1.52
  text "OTHER" at 339.33,129.165 h1.52
  text "TOLERANCE:" at 289.769,125.652 h1.52
  text "X" at 311.314,125.652 h1.52
  text "ANSI IPC-6012 TYPE 3 CLASS 2" at 315.836,125.652 h1.52
  text "OTHER +/-" at 315.835,121.989 h1.52
  text "BOW & TWIST:" at 289.769,118.302 h1.52
  text "X" at 311.314,118.302 h1.52
  text "ANSI IPC-6012 TYPE 3 CLASS 2" at 315.836,118.302 h1.52
  text "OTHER +/-" at 315.835,114.576 h1.52
  text "DRILLING:" at 287.87,111.258 h1.52
  text "NC_DRILL FILES" at 332.599,108.586 h1.52
  text "REFERENCE:" at 289.769,108.486 h1.52
  text "X" at 306.463,108.484 h1.52
  text "AS SHOWN" at 310.984,108.486 h1.52
  text "X" at 329.348,108.486 h1.52
  text "OTHER" at 340.168,104.873 h1.52
  text "PTH COPPER THICKNESS:" at 289.761,104.783 h1.52
  text "X" at 318.697,104.783 h1.52
  text "20-30 um" at 321.948,104.783 h1.52
  text "BOARD FINISH:" at 287.87,101.034 h1.52
  text "SILKSCREEN:" at 291.812,98.237 h1.52
  text "X" at 316.14,98.237 h1.52
  text "TOP" at 319.112,98.237 h1.52
  text "X" at 329.094,98.237 h1.52
  text "BOTTOM" at 332.091,98.237 h1.52
  text "SILKSCREEN COLOR:" at 291.812,94.295 h1.52
  text "X" at 316.115,94.295 h1.52
  text "WHITE" at 319.112,94.295 h1.52
  text "OTHER" at 332.091,94.295 h1.52
  text "X" at 319.442,90.652 h1.52
  text "GREEN" at 322.439,90.652 h1.52
  text "OTHER" at 338.136,90.652 h1.52
  text "SOLDER RESIST COLOR:" at 291.812,90.477 h1.52
  text "X" at 319.442,86.734 h1.52
  text "MATTE" at 322.439,86.734 h1.52
  text "SEMI-GLOSS" at 338.125,86.717 h1.52
  text "IMMERSION GOLD (ENIG)" at 314.819,82.345 h1.52
  text "ENEPIG" at 348.793,82.162 h1.52
  text "SURFACE FINISH:" at 287.87,82.136 h1.52
  text "X" at 310.298,82.136 h1.52
  text "IMM. TIN/SILVER OR EQUIV" at 296.24,78.649 h1.52
  text "OTHER" at 332.599,78.549 h1.52
  text "ARRAY/PANEL:" at 287.87,74.602 h1.52
  text "CUT AND TRIM PER M1 BOARD OUTLINE" at 314.819,74.393 h1.52
  text "N.C. ROUTE" at 314.819,70.94 h1.52
  text "X" at 332.295,70.94 h1.52
  text "V. SCORE" at 336.816,70.94 h1.52
  text "CERTIFICATION:" at 287.87,67.66 h1.52
  text "MATERIALS AND WORKMANSHIP FOR ALL PCBS" at 306.285,67.66 h1.52
  text "TO MEET OR EXCEED THE REQUIREMENTS OF:" at 306.285,65.271 h1.52
  text "X" at 297.078,62.003 h1.52
  text "ANSI IPC-A-600F CLASS ->" at 300.329,62.003 h1.52
  text "X" at 342.188,62.003 h1.52
  text "2" at 344.982,62.003 h1.52
  text "1" at 336.981,61.965 h1.52
  text "3" at 353.973,61.965 h1.52
  text "X" at 317.702,58.252 h1.52
  text "RoHS" at 320.953,58.252 h1.52
  text "OTHER" at 337.321,58.252 h1.52
  text "PER ORDER" at 347.407,58.252 h1.52
  text "ALL BOARDS MUST MEET OR EXCEED UL94-V0 REQUIREMENTS." at 288.569,54.345 h1.52
  text "PCB MUST BEAR THE UL94V-0 UL REGISTERED MATERIAL ID NUMBER" at 288.569,51.397 h1.52
  text "ADDITIONAL REQUIREMENTS:" at 287.87,47.094 h1.52
  text "MICROSECTION:" at 289.769,44.373 h1.52
  text "YES" at 312.775,44.373 h1.52
  text "REQUIRED" at 334.657,40.707 h1.52
  text "BARE BOARD ELEC. TEST:" at 289.769,40.634 h1.52
  text "NONE" at 322.935,40.634 h1.52
  text "X" at 331.66,40.634 h1.52
  text "PER ORDER" at 349.693,40.634 h1.52
  text "XX MIL VIAS REQUIRE NON-CONDUCTIVE FILL AND PLANARIZE" at 294.04,35.428 h1.5
  text "XX MIL VIAS REQUIRE CONDUCTIVE FILL AND PLANARIZE" at 294.243,32.787 h1.52
  text "OUTER XX MIL TRACES REQUIRE 50 OHM SINGLE-ENDED IMPEDANCE" at 294.218,28.637 h1.47
  text "LAYER 2 & 3 (INNER LAYERS) XX MIL WIDE, XX MIL SPACE / TRACES REQUIRE 100 OHM DIFFERENTIAL IMPEDANCE" at 294.015,22.65 h1.52
  text ".Layer_Name" at 14.656,-21.806 h1.52
M11 Gerber Information:
  lines w0.254: -7.417,-23.626 160.223,-23.626 ; -7.417,-18.462 160.274,-18.462 ; -7.417,-13.297 -7.417,-28.791 94.31,-28.791 160.274,-28.791 160.274,-13.297 -7.404,-13.297 -7.404,-28.791 32.614,-28.791 ; 55.194,-28.791 55.194,-13.297 ; 87.376,-18.462 87.376,-13.297 ; 108.712,-18.462 108.712,-13.297 ; 124.511,-28.956 124.511,-23.804
  text "ALL ARTWORK VIEWED FROM TOP SIDE" at -5.804,-16.654 h1.52
  text "BOARD #:" at 57.099,-16.654 h1.52
  text ".PRJ_Number" at 70.955,-16.654 h1.52
  text "REV:" at 92.405,-16.654 h1.52
  text ".PCB_Rev" at 99.809,-16.654 h1.52
  text "SVN REV:" at 113.69,-16.654 h1.52
  text ".VersionControl_RevNumber" at 126.543,-16.654 h1.52
  text "LAYER NAME =" at -5.804,-21.806 h1.52
  text "TID #:" at 57.099,-21.819 h1.52
  text ".TID" at 70.955,-21.819 h1.52
  text "PLOT NAME =" at -5.804,-27.034 h1.52
  text ".plot_File_Name" at 14.656,-27.034 h1.52
  text "GENERATED    :" at 57.15,-27.034 h1.52
  text ".Print_Date" at 79.235,-27.034 h1.52
  text ".Print_Time" at 97.752,-27.034 h1.52
  text "TEXAS INSTRUMENTS" at 129.87,-27.034 h1.52
M12 Stackup:
  drawing of 191 lines, arcs and shapes, not listed
  text "Layer" at 249.215,194.308 h1.52
  text "Name" at 259.626,194.308 h1.52
  text "Material" at 283.242,194.308 h1.52
  text "Thickness" at 305.08,194.308 h1.52
  text "Constant" at 321.586,194.308 h1.52
  text "Board Layer Stack" at 336.06,194.308 h1.52
  text "1" at 249.215,191.26 h1.52
  text "Top Overlay" at 259.626,191.26 h1.52
  text "2" at 249.215,188.212 h1.52
  text "Top Solder" at 259.626,188.212 h1.52
  text "Solder Resist" at 283.242,188.212 h1.52
  text "0.40mil" at 305.08,188.212 h1.52
  text "3.5" at 321.586,188.212 h1.52
  text "3" at 249.215,185.164 h1.52
  text "Top Layer" at 259.626,185.164 h1.52
  text "Copper" at 283.242,185.164 h1.52
  text "1.40mil" at 305.08,185.164 h1.52
  text "4" at 249.215,182.116 h1.52
  text "Dielectric1" at 259.626,182.116 h1.52
  text "FR-4" at 283.242,182.116 h1.52
  text "59.20mil" at 305.08,182.116 h1.52
  text "4.8" at 321.586,182.116 h1.52
  text "5" at 249.215,179.068 h1.52
  text "Bottom Layer" at 259.626,179.068 h1.52
  text "Copper" at 283.242,179.068 h1.52
  text "1.40mil" at 305.08,179.068 h1.52
  text "6" at 249.215,176.02 h1.52
  text "Bottom Solder" at 259.626,176.02 h1.52
  text "Solder Resist" at 283.242,176.02 h1.52
  text "0.40mil" at 305.08,176.02 h1.52
  text "3.5" at 321.586,176.02 h1.52
  text "7" at 249.215,172.972 h1.52
  text "Bottom Overlay" at 259.626,172.972 h1.52
  text ".Layer_Name" at 14.656,-21.806 h1.52
M13 Component Bodies Top:
  text ".Layer_Name" at 14.656,-21.806 h1.52
M14 Component Bodies Bottom:
  text ".Layer_Name" at 14.656,-21.806 h1.52
M15 Courtyards Top:
  text ".Layer_Name" at 14.656,-21.806 h1.52
M16 Courtyards Bottom:
  text ".Layer_Name" at 14.656,-21.806 h1.52
Drill Drawing:
  text ".Layer_Name" at 14.656,-21.806 h1.52
M17 Embedded Cavity:
  text ".Layer_Name" at 14.656,-21.806 h1.52
M18 Embedded Assembly:
  text ".Layer_Name" at 14.656,-21.806 h1.52
M19 Embedded Keepout:
  text ".Layer_Name" at 14.656,-21.806 h1.52

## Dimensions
0,-10.16 to 25.4,-10.16 on M2 Board Dimensions
0,0 to 0.142,42.5 on M2 Board Dimensions
0,0 to 85,0 on M2 Board Dimensions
